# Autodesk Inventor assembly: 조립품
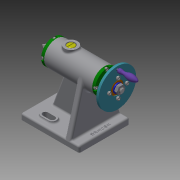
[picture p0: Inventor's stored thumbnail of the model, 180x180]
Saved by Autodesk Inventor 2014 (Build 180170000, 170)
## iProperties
Created: 2019-10
Part Number: 조립품
Document SubType Name: Assembly
Designer: kh
Author: kh
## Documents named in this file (18)
- C:\Users\kh\Desktop\491004V1031\조립품.iam
- C:\Users\kh\Desktop\491004V1031\본체.ipt
- C:\Users\kh\Desktop\491004V1031\나사.ipt
- C:\Users\kh\Desktop\491004V1031\나사축.ipt
- C:\Users\kh\Desktop\491004V1031\너트 M8.ipt
- C:\Users\kh\Desktop\491004V1031\돌림판.ipt
- C:\Users\kh\Desktop\491004V1031\멈춤나사 M3.ipt
- C:\Users\kh\Desktop\491004V1031\볼트 M3.ipt
- C:\Users\kh\Desktop\491004V1031\부시.ipt
- C:\Users\kh\Desktop\491004V1031\센터.ipt
- C:\Users\kh\Desktop\491004V1031\센터홀더.ipt
- C:\Users\kh\Desktop\491004V1031\슬리브.ipt
- C:\Users\kh\Desktop\491004V1031\와셔.ipt
- C:\Users\kh\Desktop\491004V1031\중공축.ipt
- C:\Users\kh\Desktop\491004V1031\커버.ipt
- C:\Users\kh\Desktop\491004V1031\키 4 x 4 x 10.ipt
- C:\Users\kh\Desktop\491004V1031\플랜지.ipt
- C:\Users\kh\Desktop\491004V1031\핸들.ipt
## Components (2 placed, 2 different names)
1. 플랜지:1 — Insert:4, Insert:8, Insert:9, Mate:8, Mate:9
2. 핸들:1 — Mate:5, Flush:3
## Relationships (7: Insert 3, Mate 3, Flush 1)
- Insert:4: 플랜지:1
- Insert:8: 플랜지:1
- Insert:9: 플랜지:1
- Mate:5: 핸들:1
- Flush:3: 핸들:1
- Mate:8: 플랜지:1
- Mate:9: 플랜지:1
